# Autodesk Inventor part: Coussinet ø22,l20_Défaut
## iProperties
Shininess: 64.0
Length Units: 11269
Angle Units: 11279
Time Units: 11290
Mass Units: 11283
Length Display Precision: 3
Angle Display Precision: 2
Compacted: True
Part Number: Coussinet ø22,l20_Défaut
Document SubType Name: Modeling
Created: 2006-01
Material: Par défaut
Designer: riri
Density: 0.0
Volumn: 0.0
Area: 0.0
PropertySet Name: Model Information
Control State: 0
Master: False
Checked Out: False
Author: riri
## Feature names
1. Base1
